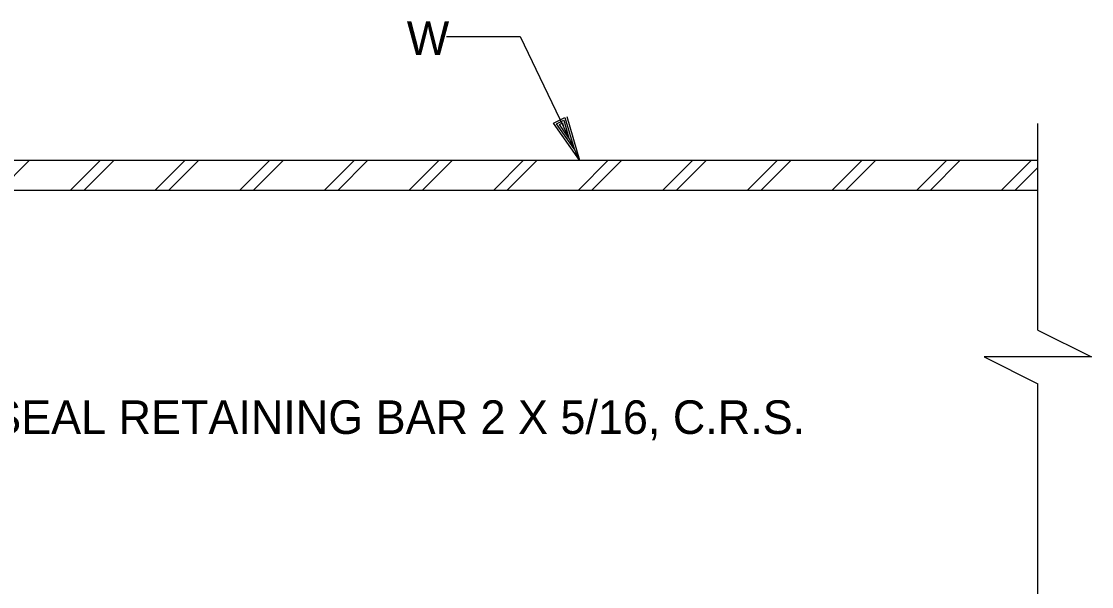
# Model space of a CAD drawing. Extents: x 22371.58 to 22374.41, y 22370.57 to 22372.4.
# Drawn here: x 22372.3521 to 22372.7247, y 22371.3 to 22371.497 of the extents above; entities that cross this region are included whole.
import ezdxf

# ---------------------------------------------------------------- set-up
doc = ezdxf.new("R2010")
doc.units = 0
for name, color, linetype in [('S-ANNO-DIMS', 7, 'Continuous'), ('S-GATE-SEAL', 7, 'Continuous'), ('S-SECT-SHPS', 7, 'Continuous')]:
    doc.layers.add(name, color=color, linetype=linetype)

msp = doc.modelspace()

# ---------------------------------------------------------------- linework, layer by layer
at = {"layer": 'S-ANNO-DIMS'}
for p, q in [((22372.500114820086, 22371.491699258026), (22372.52579190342, 22371.491699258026)), ((22372.52579190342, 22371.491699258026), (22372.546406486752, 22371.448615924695)), ((22372.70594815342, 22371.389428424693), (22372.70594815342, 22371.461428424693)), ((22372.70594815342, 22371.216615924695), (22372.70594815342, 22371.370740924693))]:
    msp.add_line(p, q, dxfattribs=at)
for points in [[(22372.54201065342, 22371.463793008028), (22372.546406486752, 22371.448615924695), (22372.53735440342, 22371.461553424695), (22372.541333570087, 22371.463459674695), (22372.544531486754, 22371.452522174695), (22372.53838565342, 22371.461313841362), (22372.54094815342, 22371.462543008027), (22372.542739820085, 22371.45628259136), (22372.539427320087, 22371.461074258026), (22372.54047940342, 22371.461574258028), (22372.540864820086, 22371.46018884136)], [(22372.70594815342, 22371.389428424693), (22372.72469815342, 22371.380115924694), (22372.687239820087, 22371.380115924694), (22372.70594815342, 22371.370740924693)]]:
    msp.add_lwpolyline(points, dxfattribs=at)
at = {"layer": 'S-GATE-SEAL'}
for p, q in [((22371.810114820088, 22371.448615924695), (22372.70594815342, 22371.448615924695)), ((22371.810114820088, 22371.438199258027), (22372.70594815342, 22371.438199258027))]:
    msp.add_line(p, q, dxfattribs=at)
at = {"layer": 'S-SECT-SHPS'}
for p, q in [((22372.544531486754, 22371.452522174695), (22372.544531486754, 22371.452522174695)), ((22372.546406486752, 22371.448615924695), (22372.546406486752, 22371.448615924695))]:
    msp.add_line(p, q, dxfattribs=at)
for points in [[(22372.344468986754, 22371.43818884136), (22372.354896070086, 22371.448615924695)], [(22372.369218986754, 22371.43818884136), (22372.379646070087, 22371.448615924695)], [(22372.373937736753, 22371.438199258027), (22372.38435440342, 22371.448615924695)], [(22372.398687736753, 22371.438199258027), (22372.409104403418, 22371.448615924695)], [(22372.403396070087, 22371.438199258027), (22372.41381273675, 22371.448615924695)], [(22372.428146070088, 22371.43818884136), (22372.438562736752, 22371.448615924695)], [(22372.432864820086, 22371.43818884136), (22372.443281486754, 22371.448615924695)], [(22372.457614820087, 22371.438199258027), (22372.46803148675, 22371.448615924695)], [(22372.46232315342, 22371.438199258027), (22372.472739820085, 22371.448615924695)], [(22372.487073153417, 22371.438199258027), (22372.497489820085, 22371.448615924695)], [(22372.49179190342, 22371.438199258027), (22372.502208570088, 22371.448615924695)], [(22372.51653148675, 22371.438199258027), (22372.52694815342, 22371.448615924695)], [(22372.521250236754, 22371.438199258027), (22372.53166690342, 22371.448615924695)], [(22372.54600023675, 22371.438199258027), (22372.55641690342, 22371.448615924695)], [(22372.550708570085, 22371.438199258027), (22372.56113565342, 22371.448615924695)], [(22372.575458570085, 22371.438199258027), (22372.585885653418, 22371.448615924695)], [(22372.580177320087, 22371.43818884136), (22372.59059398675, 22371.448615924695)], [(22372.604927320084, 22371.438199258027), (22372.615343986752, 22371.448615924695)], [(22372.609635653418, 22371.438199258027), (22372.620052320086, 22371.448615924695)], [(22372.63438565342, 22371.438199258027), (22372.644802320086, 22371.448615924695)], [(22372.63910440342, 22371.438199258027), (22372.649521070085, 22371.448615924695)], [(22372.663854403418, 22371.438199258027), (22372.674271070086, 22371.448615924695)], [(22372.66856273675, 22371.438199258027), (22372.67897940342, 22371.448615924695)], [(22372.693312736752, 22371.43818884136), (22372.70372940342, 22371.448615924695)], [(22372.698031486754, 22371.438199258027), (22372.70594815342, 22371.446115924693)]]:
    msp.add_lwpolyline(points, dxfattribs=at)

# ---------------------------------------------------------------- texts
at = {"layer": 'S-ANNO-DIMS'}
for s, p in [('W', (22372.486271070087, 22371.485272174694)), ('SEAL RETAINING BAR 2 X 5/16, C.R.S.', (22372.341562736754, 22371.353230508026))]:
    msp.add_text(s, height=0.011697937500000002, dxfattribs=at).set_placement(p)

doc.saveas('drawing.dxf')
